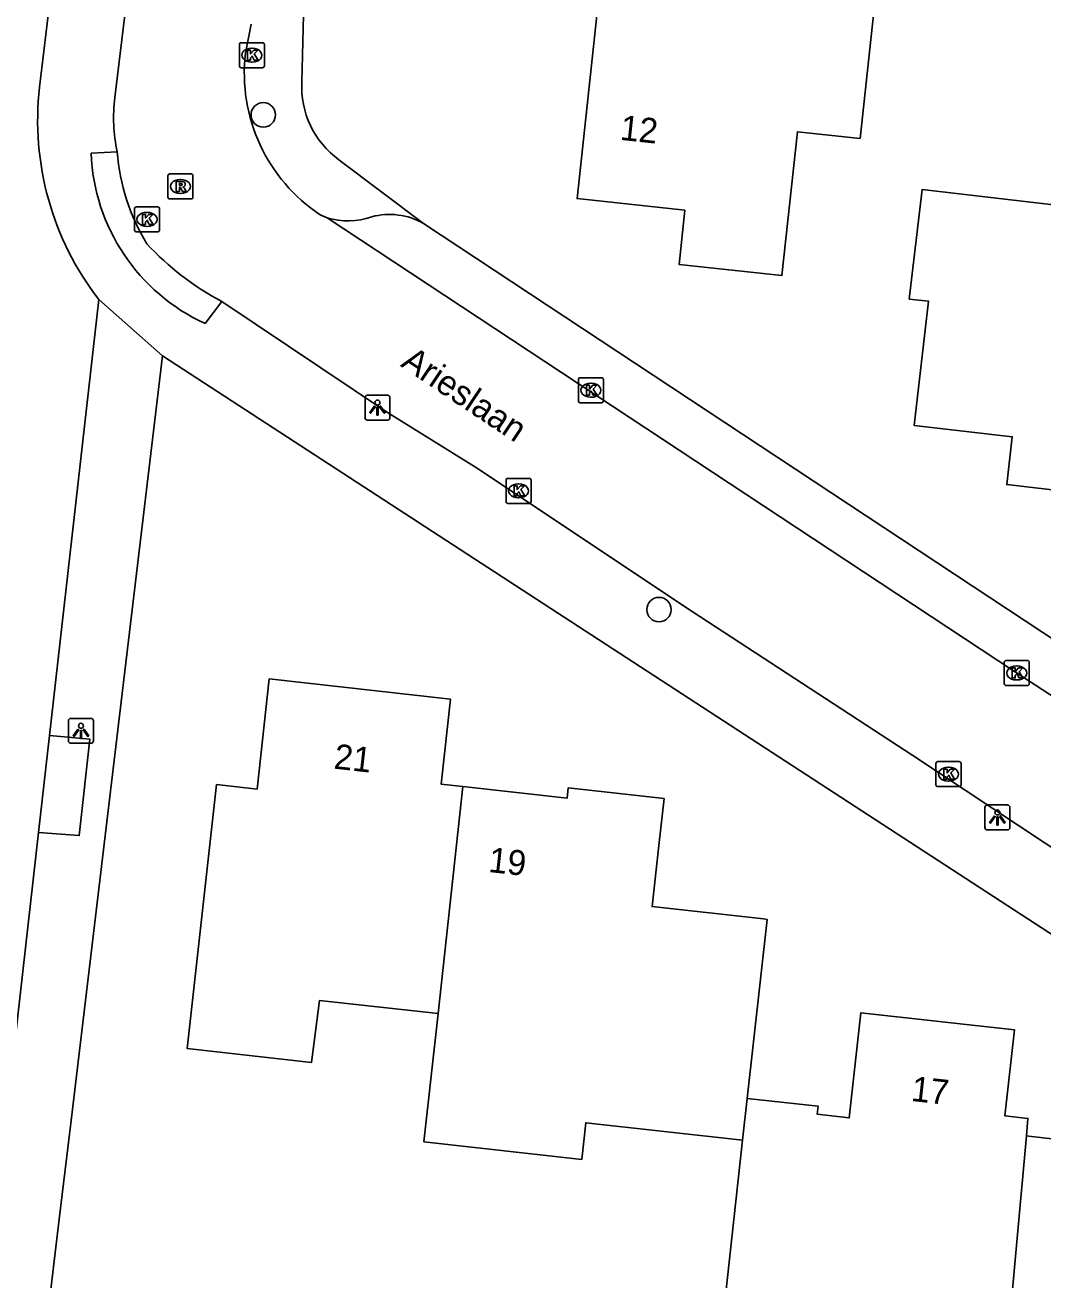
# Model space of a CAD drawing. Extents: x 162398 to 163643, y 386453 to 387397.
# Drawn here: x 162934 to 162974.7, y 386818.2 to 386868.4 of the extents above; entities that cross this region are included whole.
import ezdxf

# ---------------------------------------------------------------- set-up
doc = ezdxf.new("R2010")
doc.units = 0
for name, color, linetype in [('IMGEO_Boom', 7, 'Continuous'), ('IMGEO_Groenvoorziening', 7, 'Continuous'), ('IMGEO_Kolk', 7, 'Continuous'), ('IMGEO_Lichtpunt', 7, 'Continuous'), ('IMGEO_Openbare_ruimte_label', 7, 'Continuous'), ('IMGEO_Pand', 7, 'Continuous'), ('IMGEO_Pand_nummerreeks', 7, 'Continuous'), ('IMGEO_Parkeervlak_open', 7, 'Continuous'), ('IMGEO_Rijbaan_lokaal_open', 7, 'Continuous'), ('IMGEO_Rioolput', 7, 'Continuous'), ('IMGEO_Voetpad_halfverhard', 7, 'Continuous'), ('IMGEO_Voetpad_open', 7, 'Continuous')]:
    doc.layers.add(name, color=color, linetype=linetype)

msp = doc.modelspace()

# ---------------------------------------------------------------- linework, layer by layer
at = {"layer": 'IMGEO_Boom'}
for centre in [(162943.528, 386864.763), (162959.353, 386844.985)]:
    msp.add_circle(centre, 0.489, dxfattribs=at)
at = {"layer": 'IMGEO_Groenvoorziening'}
msp.add_lwpolyline([(162934.537, 386836.069), (162934.978, 386839.955)], dxfattribs=at)
at = {"layer": 'IMGEO_Kolk'}
for p, q in [((162942.574, 386866.723), (162942.574, 386867.575)), ((162942.649, 386867.649), (162943.501, 386867.649)), ((162943.062, 386867.429), (162943.087, 386867.429)), ((162943.575, 386867.575), (162943.575, 386866.723)), ((162943.501, 386866.649), (162942.649, 386866.649)), ((162943.085, 386866.869), (162943.06, 386866.869)), ((162938.379, 386860.159), (162938.379, 386861.011)), ((162938.454, 386861.085), (162939.306, 386861.085)), ((162939.38, 386861.011), (162939.38, 386860.159)), ((162938.867, 386860.865), (162938.892, 386860.865)), ((162939.306, 386860.085), (162938.454, 386860.085)), ((162938.89, 386860.305), (162938.865, 386860.305)), ((162956.129, 386853.328), (162956.129, 386854.18)), ((162956.204, 386854.254), (162957.056, 386854.254)), ((162956.617, 386854.034), (162956.642, 386854.034)), ((162957.13, 386854.18), (162957.13, 386853.328)), ((162956.64, 386853.474), (162956.615, 386853.474)), ((162957.056, 386853.254), (162956.204, 386853.254)), ((162953.237, 386849.306), (162953.237, 386850.158)), ((162953.312, 386850.232), (162954.164, 386850.232)), ((162953.725, 386850.012), (162953.75, 386850.012)), ((162954.238, 386850.158), (162954.238, 386849.306)), ((162953.748, 386849.452), (162953.723, 386849.452)), ((162954.164, 386849.232), (162953.312, 386849.232)), ((162973.157, 386842.025), (162973.157, 386842.877)), ((162973.232, 386842.951), (162974.084, 386842.951)), ((162974.158, 386842.877), (162974.158, 386842.025)), ((162973.645, 386842.731), (162973.67, 386842.731)), ((162974.084, 386841.951), (162973.232, 386841.951)), ((162973.668, 386842.171), (162973.643, 386842.171)), ((162970.428, 386837.981), (162970.428, 386838.833)), ((162970.503, 386838.907), (162971.355, 386838.907)), ((162971.429, 386838.833), (162971.429, 386837.981)), ((162970.916, 386838.687), (162970.941, 386838.687)), ((162971.355, 386837.907), (162970.503, 386837.907)), ((162970.939, 386838.127), (162970.914, 386838.127))]:
    msp.add_line(p, q, dxfattribs=at)
for points in [[(162942.574, 386866.723), (162942.574, 386867.575)], [(162942.649, 386867.649), (162943.501, 386867.649)], [(162943.575, 386867.575), (162943.575, 386866.723)], [(162942.895, 386867.349), (162943.018, 386867.349), (162943.018, 386867.198), (162943.148, 386867.349), (162943.312, 386867.349), (162943.166, 386867.198), (162943.319, 386866.949), (162943.167, 386866.949), (162943.082, 386867.113), (162943.018, 386867.046), (162943.018, 386866.949), (162942.895, 386866.949), (162942.895, 386867.349)], [(162943.501, 386866.649), (162942.649, 386866.649)], [(162938.379, 386860.159), (162938.379, 386861.011)], [(162938.454, 386861.085), (162939.306, 386861.085)], [(162939.38, 386861.011), (162939.38, 386860.159)], [(162938.7, 386860.785), (162938.823, 386860.785), (162938.823, 386860.634), (162938.953, 386860.785), (162939.117, 386860.785), (162938.971, 386860.634), (162939.124, 386860.385), (162938.972, 386860.385), (162938.887, 386860.549), (162938.823, 386860.482), (162938.823, 386860.385), (162938.7, 386860.385), (162938.7, 386860.785)], [(162939.306, 386860.085), (162938.454, 386860.085)], [(162956.129, 386853.328), (162956.129, 386854.18)], [(162956.204, 386854.254), (162957.056, 386854.254)], [(162956.45, 386853.954), (162956.573, 386853.954), (162956.573, 386853.803), (162956.703, 386853.954), (162956.867, 386853.954), (162956.721, 386853.803), (162956.874, 386853.554), (162956.722, 386853.554), (162956.637, 386853.718), (162956.573, 386853.651), (162956.573, 386853.554), (162956.45, 386853.554), (162956.45, 386853.954)], [(162957.13, 386854.18), (162957.13, 386853.328)], [(162957.056, 386853.254), (162956.204, 386853.254)], [(162953.237, 386849.306), (162953.237, 386850.158)], [(162953.312, 386850.232), (162954.164, 386850.232)], [(162953.558, 386849.932), (162953.681, 386849.932), (162953.681, 386849.781), (162953.811, 386849.932), (162953.975, 386849.932), (162953.829, 386849.781), (162953.982, 386849.532), (162953.83, 386849.532), (162953.745, 386849.696), (162953.681, 386849.629), (162953.681, 386849.532), (162953.558, 386849.532), (162953.558, 386849.932)], [(162954.238, 386850.158), (162954.238, 386849.306)], [(162954.164, 386849.232), (162953.312, 386849.232)], [(162973.157, 386842.025), (162973.157, 386842.877)], [(162973.232, 386842.951), (162974.084, 386842.951)], [(162974.158, 386842.877), (162974.158, 386842.025)], [(162973.478, 386842.651), (162973.601, 386842.651), (162973.601, 386842.5), (162973.731, 386842.651), (162973.895, 386842.651), (162973.749, 386842.5), (162973.902, 386842.251), (162973.75, 386842.251), (162973.665, 386842.415), (162973.601, 386842.348), (162973.601, 386842.251), (162973.478, 386842.251), (162973.478, 386842.651)], [(162974.084, 386841.951), (162973.232, 386841.951)], [(162970.428, 386837.981), (162970.428, 386838.833)], [(162970.503, 386838.907), (162971.355, 386838.907)], [(162971.429, 386838.833), (162971.429, 386837.981)], [(162970.749, 386838.607), (162970.872, 386838.607), (162970.872, 386838.456), (162971.002, 386838.607), (162971.166, 386838.607), (162971.02, 386838.456), (162971.173, 386838.207), (162971.021, 386838.207), (162970.936, 386838.371), (162970.872, 386838.304), (162970.872, 386838.207), (162970.749, 386838.207), (162970.749, 386838.607)], [(162971.355, 386837.907), (162970.503, 386837.907)]]:
    msp.add_lwpolyline(points, dxfattribs=at)
for centre, start, end in [((162942.651, 386867.573), 91.552, 178.448), ((162942.651, 386867.573), 91.552, 178.448), ((162943.499, 386867.573), 1.552, 88.448), ((162943.499, 386867.573), 1.552, 88.448), ((162942.651, 386866.725), 181.552, 268.448), ((162942.651, 386866.725), 181.552, 268.448), ((162943.499, 386866.725), 271.552, 358.448), ((162943.499, 386866.725), 271.552, 358.448), ((162938.456, 386861.009), 91.552, 178.448), ((162938.456, 386861.009), 91.552, 178.448), ((162939.304, 386861.009), 1.552, 88.448), ((162939.304, 386861.009), 1.552, 88.448), ((162938.456, 386860.161), 181.552, 268.448), ((162938.456, 386860.161), 181.552, 268.448), ((162939.304, 386860.161), 271.552, 358.448), ((162939.304, 386860.161), 271.552, 358.448), ((162956.206, 386854.178), 91.552, 178.448), ((162956.206, 386854.178), 91.552, 178.448), ((162957.054, 386854.178), 1.552, 88.448), ((162957.054, 386854.178), 1.552, 88.448), ((162956.206, 386853.33), 181.552, 268.448), ((162956.206, 386853.33), 181.552, 268.448), ((162957.054, 386853.33), 271.552, 358.448), ((162957.054, 386853.33), 271.552, 358.448), ((162953.314, 386850.156), 91.552, 178.448), ((162953.314, 386850.156), 91.552, 178.448), ((162954.162, 386850.156), 1.552, 88.448), ((162954.162, 386850.156), 1.552, 88.448), ((162953.314, 386849.308), 181.552, 268.448), ((162953.314, 386849.308), 181.552, 268.448), ((162954.162, 386849.308), 271.552, 358.448), ((162954.162, 386849.308), 271.552, 358.448), ((162973.234, 386842.875), 91.552, 178.448), ((162973.234, 386842.875), 91.552, 178.448), ((162974.082, 386842.875), 1.552, 88.448), ((162974.082, 386842.875), 1.552, 88.448), ((162973.234, 386842.027), 181.552, 268.448), ((162973.234, 386842.027), 181.552, 268.448), ((162974.082, 386842.027), 271.552, 358.448), ((162974.082, 386842.027), 271.552, 358.448), ((162970.505, 386838.831), 91.552, 178.448), ((162970.505, 386838.831), 91.552, 178.448), ((162971.353, 386838.831), 1.552, 88.448), ((162971.353, 386838.831), 1.552, 88.448), ((162970.505, 386837.983), 181.552, 268.448), ((162970.505, 386837.983), 181.552, 268.448), ((162971.353, 386837.983), 271.552, 358.448), ((162971.353, 386837.983), 271.552, 358.448)]:
    msp.add_arc(centre, 0.0765, start, end, dxfattribs=at)
for centre, major_axis, ratio, start_param, end_param in [((162943.061, 386867.149), (-0.387, 0.002), 0.722429, 4.712389, 7.853982), ((162943.086, 386867.149), (-0.39, 0.002), 0.717154, 1.570796, 4.712389), ((162938.866, 386860.585), (-0.387, 0.002), 0.722429, 4.712389, 7.853982), ((162938.891, 386860.585), (-0.39, 0.002), 0.717154, 1.570796, 4.712389), ((162956.616, 386853.754), (-0.387, 0.002), 0.722429, 4.712389, 7.853982), ((162956.641, 386853.754), (-0.39, 0.002), 0.717154, 1.570796, 4.712389), ((162953.724, 386849.732), (-0.387, 0.002), 0.722429, 4.712389, 7.853982), ((162953.749, 386849.732), (-0.39, 0.002), 0.717154, 1.570796, 4.712389), ((162973.644, 386842.451), (-0.387, 0.002), 0.722429, 4.712389, 7.853982), ((162973.669, 386842.451), (-0.39, 0.002), 0.717154, 1.570796, 4.712389), ((162970.915, 386838.407), (-0.387, 0.002), 0.722429, 4.712389, 7.853982), ((162970.94, 386838.407), (-0.39, 0.002), 0.717154, 1.570796, 4.712389)]:
    msp.add_ellipse(centre, major_axis=major_axis, ratio=ratio, start_param=start_param, end_param=end_param, dxfattribs=at)
at = {"layer": 'IMGEO_Lichtpunt'}
for p, q in [((162947.597, 386853.461), (162947.597, 386852.654)), ((162947.597, 386853.461), (162947.597, 386852.654)), ((162948.499, 386853.556), (162947.691, 386853.556)), ((162948.499, 386853.556), (162947.691, 386853.556)), ((162948.593, 386852.654), (162948.593, 386853.461)), ((162948.593, 386852.654), (162948.593, 386853.461)), ((162947.691, 386852.56), (162948.499, 386852.56)), ((162947.691, 386852.56), (162948.499, 386852.56)), ((162935.74, 386840.541), (162935.74, 386839.734)), ((162935.74, 386840.541), (162935.74, 386839.734)), ((162936.642, 386840.636), (162935.834, 386840.636)), ((162936.642, 386840.636), (162935.834, 386840.636)), ((162936.736, 386839.734), (162936.736, 386840.541)), ((162936.736, 386839.734), (162936.736, 386840.541)), ((162935.834, 386839.64), (162936.642, 386839.64)), ((162935.834, 386839.64), (162936.642, 386839.64)), ((162972.388, 386837.078), (162972.388, 386836.271)), ((162972.388, 386837.078), (162972.388, 386836.271)), ((162973.29, 386837.173), (162972.482, 386837.173)), ((162973.29, 386837.173), (162972.482, 386837.173)), ((162973.384, 386836.271), (162973.384, 386837.078)), ((162973.384, 386836.271), (162973.384, 386837.078)), ((162972.482, 386836.177), (162973.29, 386836.177)), ((162972.482, 386836.177), (162973.29, 386836.177))]:
    msp.add_line(p, q, dxfattribs=at)
for points in [[(162947.971, 386853.125), (162948.01, 386853.097), (162947.822, 386852.835), (162947.784, 386852.862), (162947.971, 386853.125)], [(162948.073, 386853.077), (162948.12, 386853.077), (162948.12, 386852.755), (162948.073, 386852.755), (162948.073, 386853.077)], [(162948.183, 386853.097), (162948.221, 386853.124), (162948.408, 386852.862), (162948.369, 386852.834), (162948.183, 386853.097)], [(162936.114, 386840.205), (162936.153, 386840.177), (162935.965, 386839.915), (162935.927, 386839.942), (162936.114, 386840.205)], [(162936.216, 386840.157), (162936.263, 386840.157), (162936.263, 386839.835), (162936.216, 386839.835), (162936.216, 386840.157)], [(162936.326, 386840.177), (162936.364, 386840.204), (162936.551, 386839.942), (162936.512, 386839.914), (162936.326, 386840.177)], [(162972.762, 386836.742), (162972.801, 386836.714), (162972.613, 386836.452), (162972.575, 386836.479), (162972.762, 386836.742)], [(162972.864, 386836.694), (162972.911, 386836.694), (162972.911, 386836.372), (162972.864, 386836.372), (162972.864, 386836.694)], [(162972.974, 386836.714), (162973.012, 386836.741), (162973.199, 386836.479), (162973.16, 386836.451), (162972.974, 386836.714)]]:
    msp.add_lwpolyline(points, dxfattribs=at)
for centre in [(162948.096, 386853.259), (162936.239, 386840.339), (162972.887, 386836.876)]:
    msp.add_circle(centre, 0.0994, dxfattribs=at)
for centre, start, end in [((162947.691, 386853.461), 90, 180), ((162947.691, 386853.461), 90, 180), ((162948.499, 386853.461), 0, 90), ((162948.499, 386853.461), 0, 90), ((162947.691, 386852.654), 180, 270), ((162947.691, 386852.654), 180, 270), ((162948.499, 386852.654), 270, 0), ((162948.499, 386852.654), 270, 360), ((162935.834, 386840.541), 90, 180), ((162935.834, 386840.541), 90, 180), ((162936.642, 386840.541), 0, 90), ((162936.642, 386840.541), 0, 90), ((162935.834, 386839.734), 180, 270), ((162935.834, 386839.734), 180, 270), ((162936.642, 386839.734), 270, 0), ((162936.642, 386839.734), 270, 360), ((162972.482, 386837.078), 90, 180), ((162972.482, 386837.078), 90, 180), ((162973.29, 386837.078), 0, 90), ((162973.29, 386837.078), 0, 90), ((162972.482, 386836.271), 180, 270), ((162972.482, 386836.271), 180, 270), ((162973.29, 386836.271), 270, 0), ((162973.29, 386836.271), 270, 360)]:
    msp.add_arc(centre, 0.0946, start, end, dxfattribs=at)
at = {"layer": 'IMGEO_Pand'}
for points in [[(162967.396, 386863.816), (162964.887, 386864.086), (162964.269, 386858.339), (162960.157, 386858.782), (162960.391, 386860.951), (162956.074, 386861.416), (162957.25, 386872.341), (162962.832, 386871.74), (162962.944, 386872.782), (162968.298, 386872.206), (162968.036, 386869.768), (162967.396, 386863.816)], [(162980.651, 386849.94), (162980.557, 386849.129), (162973.258, 386849.981), (162973.481, 386851.893), (162969.553, 386852.351), (162970.132, 386857.311), (162969.36, 386857.4), (162969.871, 386861.777), (162976.149, 386861.045), (162976.353, 386861.862), (162976.686, 386862.461), (162976.968, 386862.96), (162977.384, 386863.442), (162977.916, 386863.958), (162978.481, 386864.341), (162979.179, 386864.623), (162979.711, 386864.773), (162980.201, 386864.815), (162982.347, 386864.564), (162982.113, 386862.549)], [(162950.516, 386828.836), (162945.781, 386829.363), (162945.458, 386826.885), (162940.488, 386827.438), (162941.661, 386837.987), (162943.281, 386837.807), (162943.771, 386842.214), (162951.015, 386841.409), (162950.637, 386838.007), (162951.511, 386837.91)], [(162950.516, 386828.836), (162951.511, 386837.91)], [(162951.511, 386837.91), (162955.681, 386837.447), (162955.726, 386837.857), (162959.554, 386837.432), (162959.346, 386835.559), (162959.074, 386833.114), (162963.529, 386832.619), (162963.678, 386832.602), (162962.882, 386825.444)], [(162962.693, 386823.773), (162956.424, 386824.47), (162956.263, 386823.006), (162949.953, 386823.708), (162950.516, 386828.836)], [(162962.882, 386825.444), (162965.719, 386825.128), (162965.684, 386824.808), (162966.959, 386824.666), (162967.426, 386828.866), (162973.571, 386828.183), (162973.188, 386824.742), (162974.106, 386824.641), (162974.043, 386823.947)], [(162962.882, 386825.444), (162962.693, 386823.773)], [(162973.292, 386815.62), (162968.082, 386816.199), (162967.993, 386815.401), (162966.514, 386815.566), (162966.034, 386811.238), (162961.367, 386811.756), (162961.845, 386816.085), (162961.994, 386817.437), (162962.693, 386823.773)], [(162973.292, 386815.62), (162974.043, 386823.947)], [(162974.043, 386823.947), (162974.242, 386823.925), (162975.077, 386823.832), (162978.573, 386823.442), (162978.531, 386823.062), (162981.47, 386822.735), (162980.97, 386818.233), (162985.237, 386817.879), (162984.57, 386811.886)]]:
    msp.add_lwpolyline(points, dxfattribs=at)
at = {"layer": 'IMGEO_Parkeervlak_open'}
msp.add_lwpolyline([(162949.934, 386860.424), (162987.453, 386835.647), (162991.369, 386833.385), (163000, 386829.829), (163008.342, 386828.004), (163031.625, 386825.406)], dxfattribs=at)
at = {"layer": 'IMGEO_Rijbaan_lokaal_open'}
for points in [[(162937.589, 386865.46), (162939.021, 386877.229), (162939.886, 386885.538), (162941.725, 386902.382)], [(162942.818, 386867.223), (162943.044, 386868.395)], [(162946.079, 386860.649), (162945.809, 386860.764)], [(163030.795, 386823.548), (163007.424, 386826.218), (163000, 386827.886), (162999.094, 386828.09), (162990.37, 386831.778), (162986.474, 386834.111), (162973.567, 386842.509), (162946.079, 386860.649)], [(162989.979, 386826.272), (162986.906, 386827.823), (162983.289, 386830.03), (162969.499, 386839.152), (162960.676, 386844.902), (162952.017, 386850.682), (162948.497, 386852.867), (162941.868, 386857.301)]]:
    msp.add_lwpolyline(points, dxfattribs=at)
for centre, radius, start, end in [((162949.564, 386866.425), 6.793, 173.2533, 236.442), ((162944.33, 386864.669), 6.787, 173.3081, 191.792), ((162945.917, 386863.917), 8.256, 184.4083, 211.4184), ((162947.26, 386867.386), 11.436, 222.819, 241.8666)]:
    msp.add_arc(centre, radius, start, end, dxfattribs=at)
at = {"layer": 'IMGEO_Rioolput'}
for p, q in [((162939.79, 386862.401), (162940.642, 386862.401)), ((162939.715, 386861.475), (162939.715, 386862.327)), ((162940.203, 386862.181), (162940.228, 386862.181)), ((162940.716, 386862.327), (162940.716, 386861.475)), ((162940.642, 386861.401), (162939.79, 386861.401)), ((162940.226, 386861.621), (162940.201, 386861.621))]:
    msp.add_line(p, q, dxfattribs=at)
for points in [[(162939.79, 386862.401), (162940.642, 386862.401)], [(162939.715, 386861.475), (162939.715, 386862.327)], [(162940.304, 386862.099), (162940.052, 386862.101), (162940.052, 386861.701)], [(162940.23, 386862.02), (162940.176, 386862.02), (162940.176, 386861.939)], [(162940.176, 386861.939), (162940.228, 386861.939)], [(162940.716, 386862.327), (162940.716, 386861.475)], [(162940.642, 386861.401), (162939.79, 386861.401)], [(162940.052, 386861.701), (162940.176, 386861.701), (162940.176, 386861.863), (162940.187, 386861.863)], [(162940.234, 386861.834), (162940.305, 386861.701), (162940.445, 386861.701), (162940.38, 386861.827)]]:
    msp.add_lwpolyline(points, dxfattribs=at)
for centre, radius, start, end in [((162939.792, 386862.325), 0.0765, 91.552, 178.448), ((162939.792, 386862.325), 0.0765, 91.552, 178.448), ((162940.64, 386862.325), 0.0765, 1.552, 88.448), ((162940.64, 386862.325), 0.0765, 1.552, 88.448), ((162940.212, 386862.128), 0.19, 274.7715, 282.9687), ((162940.236, 386861.924), 0.0964, 77.0061, 93.1865), ((162940.25, 386861.981), 0.0378, 276.6634, 79.6772), ((162940.303, 386861.989), 0.109, 350.3612, 89.416), ((162940.301, 386861.989), 0.112, 277.5842, 350.9817), ((162939.792, 386861.477), 0.0765, 181.552, 268.448), ((162939.792, 386861.477), 0.0765, 181.552, 268.448), ((162940.186, 386861.81), 0.0533, 26.0293, 88.6989), ((162940.285, 386861.774), 0.108, 29.5134, 73.7905), ((162940.64, 386861.477), 0.0765, 271.552, 358.448), ((162940.64, 386861.477), 0.0765, 271.552, 358.448)]:
    msp.add_arc(centre, radius, start, end, dxfattribs=at)
for centre, major_axis, ratio, start_param, end_param in [((162940.202, 386861.901), (-0.387, 0.002), 0.722429, 4.712389, 7.853982), ((162940.227, 386861.901), (-0.39, 0.002), 0.717154, 1.570796, 4.712389)]:
    msp.add_ellipse(centre, major_axis=major_axis, ratio=ratio, start_param=start_param, end_param=end_param, dxfattribs=at)
at = {"layer": 'IMGEO_Voetpad_halfverhard'}
for points in [[(162934.978, 386839.955), (162936.953, 386857.379)], [(162939.497, 386855.132), (162935.841, 386824.556), (162935.369, 386820.614), (162931.696, 386789.898)], [(162934.978, 386839.955), (162936.598, 386839.8), (162936.17, 386835.952), (162934.537, 386836.069)], [(162931.981, 386813.464), (162932.233, 386815.736), (162934.537, 386836.069)]]:
    msp.add_lwpolyline(points, dxfattribs=at)
at = {"layer": 'IMGEO_Voetpad_open'}
for points in [[(162934.584, 386865.872), (162939.133, 386903.732)], [(162945.201, 386871.425), (162945.072, 386866.088)], [(162936.642, 386863.23), (162937.686, 386863.282)], [(162946.556, 386862.969), (162949.934, 386860.424)], [(162936.953, 386857.379), (162939.497, 386855.132)], [(162941.868, 386857.301), (162941.199, 386856.421)], [(162939.497, 386855.132), (162983.26, 386826.659)]]:
    msp.add_lwpolyline(points, dxfattribs=at)
for centre, radius, start, end in [((162948.663, 386865.884), 3.597, 176.7513, 234.1383), ((162946.19, 386864.532), 11.683, 173.416, 217.7553), ((162944.473, 386863.541), 7.837, 182.2778, 245.3079), ((162946.911, 386863.363), 2.839, 252.9515, 289.6757), ((162948.575, 386858.028), 2.754, 60.4368, 104.8972)]:
    msp.add_arc(centre, radius, start, end, dxfattribs=at)

# ---------------------------------------------------------------- texts
at = {"layer": 'IMGEO_Openbare_ruimte_label'}
msp.add_text('Arieslaan', height=1, rotation=326.3417, dxfattribs=at).set_placement((162948.982, 386854.732))
at = {"layer": 'IMGEO_Pand_nummerreeks'}
for s, rotation, p in [('12', 353.8522, (162957.769, 386863.768)), ('21', 353.6589, (162946.322, 386838.63)), ('19', 353.6915, (162952.505, 386834.498)), ('17', 353.6574, (162969.405, 386825.345))]:
    msp.add_text(s, height=1, rotation=rotation, dxfattribs=at).set_placement(p)

doc.saveas('drawing.dxf')
